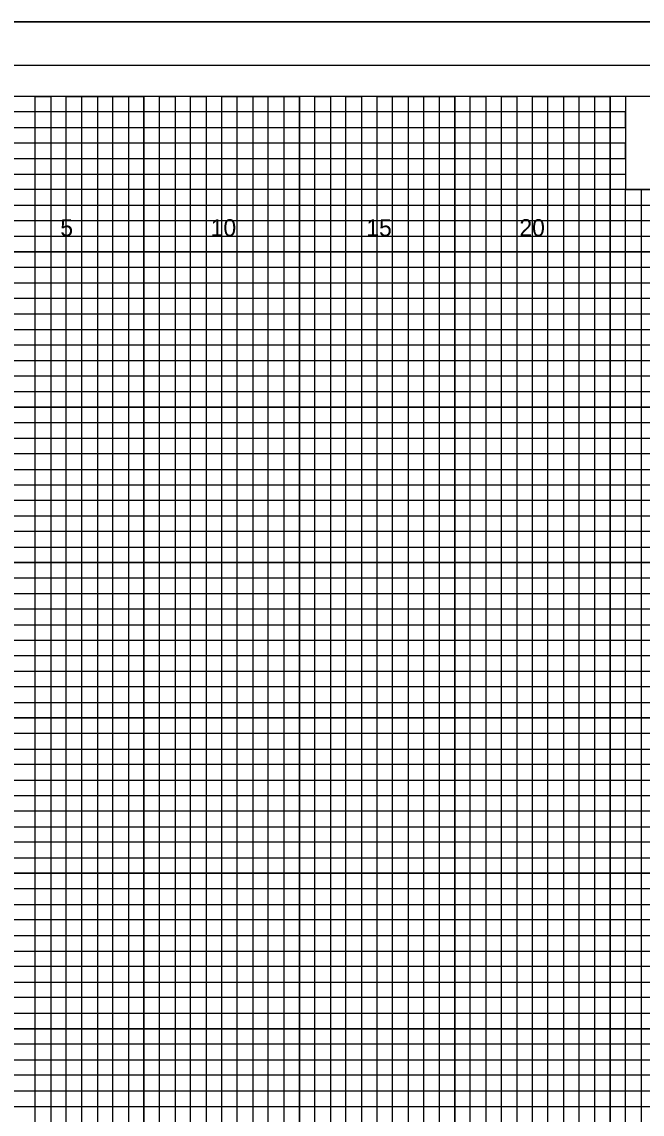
# Model space of a CAD drawing. Extents: x -4 to 103, y -2 to 209.
# Drawn here: x 54.82 to 74.78, y 103.08 to 138.22 of the extents above; entities that cross this region are included whole.
import ezdxf

# ---------------------------------------------------------------- set-up
doc = ezdxf.new("R2010")
doc.units = 0
for name, color, linetype in [('Old_Level_10', 7, 'Continuous'), ('Old_Level_16', 7, 'Continuous'), ('Old_Level_17', 7, 'Continuous'), ('Old_Level_3', 7, 'Continuous'), ('Old_Level_5', 7, 'Continuous'), ('Old_Level_6', 7, 'Continuous'), ('Old_Level_8', 7, 'Continuous'), ('Typical Curb CELL', 7, 'Continuous')]:
    doc.layers.add(name, color=color, linetype=linetype)

msp = doc.modelspace()

# ---------------------------------------------------------------- linework, layer by layer
at = {"layer": 'Old_Level_10'}
for p, q in [((56.25, 70.825), (56.25, 135.825)), ((58.75, 70.825), (58.75, 135.825)), ((61.25, 70.825), (61.25, 135.825)), ((63.75, 70.825), (63.75, 135.825)), ((66.25, 70.825), (66.25, 135.825)), ((68.75, 70.825), (68.75, 135.825)), ((71.25, 70.825), (71.25, 135.825)), ((73.75, 70.825), (73.75, 135.825)), ((0, 133.325), (74.25, 133.325)), ((0, 130.825), (102.5, 130.825)), ((0, 128.325), (102.5, 128.325)), ((0, 125.825), (102.5, 125.825)), ((0, 123.325), (102.5, 123.325)), ((0, 120.825), (102.5, 120.825)), ((0, 118.325), (102.5, 118.325)), ((0, 115.825), (102.5, 115.825)), ((0, 113.325), (102.5, 113.325)), ((0, 110.825), (102.5, 110.825)), ((0, 108.325), (102.5, 108.325)), ((0, 105.825), (102.5, 105.825)), ((0, 103.325), (102.5, 103.325))]:
    msp.add_line(p, q, dxfattribs=at)
at = {"layer": 'Old_Level_17'}
for points in [[(55.25, 70.825), (55.25, 135.825), (55.75, 135.825), (55.75, 70.825)], [(56.75, 70.825), (56.75, 135.825), (57.25, 135.825), (57.25, 70.825)], [(57.75, 70.825), (57.75, 135.825), (58.25, 135.825), (58.25, 70.825)], [(59.25, 70.825), (59.25, 135.825), (59.75, 135.825), (59.75, 70.825)], [(60.25, 70.825), (60.25, 135.825), (60.75, 135.825), (60.75, 70.825)], [(61.75, 70.825), (61.75, 135.825), (62.25, 135.825), (62.25, 70.825)], [(62.75, 70.825), (62.75, 135.825), (63.25, 135.825), (63.25, 70.825)], [(64.25, 70.825), (64.25, 135.825), (64.75, 135.825), (64.75, 70.825)], [(65.25, 70.825), (65.25, 135.825), (65.75, 135.825), (65.75, 70.825)], [(66.75, 70.825), (66.75, 135.825), (67.25, 135.825), (67.25, 70.825)], [(67.75, 70.825), (67.75, 135.825), (68.25, 135.825), (68.25, 70.825)], [(69.25, 70.825), (69.25, 135.825)], [(69.25, 135.825), (69.75, 135.825), (69.75, 70.825)], [(70.25, 70.825), (70.25, 135.825), (70.75, 135.825), (70.75, 70.825)], [(71.75, 70.825), (71.75, 135.825), (72.25, 135.825), (72.25, 70.825)], [(72.75, 70.825), (72.75, 135.825), (73.25, 135.825), (73.25, 70.825)], [(0, 132.825), (0, 133.825), (74.25, 133.825), (74.25, 134.325), (0, 134.325), (0, 134.825), (74.25, 134.825), (74.25, 135.325), (0, 135.325)], [(0, 132.325), (102.5, 132.325), (102.5, 132.825), (0, 132.825)], [(74.25, 70.825), (74.25, 132.825), (74.75, 132.825), (74.75, 70.825)], [(0, 131.325), (102.5, 131.325), (102.5, 131.825), (0, 131.825)], [(0, 129.825), (102.5, 129.825), (102.5, 130.325), (0, 130.325)], [(0, 128.825), (102.5, 128.825), (102.5, 129.325), (0, 129.325)], [(0, 127.325), (102.5, 127.325), (102.5, 127.825), (0, 127.825)], [(0, 126.325), (102.5, 126.325), (102.5, 126.825), (0, 126.825)], [(0, 124.825), (102.5, 124.825), (102.5, 125.325), (0, 125.325)], [(0, 123.825), (102.5, 123.825), (102.5, 124.325), (0, 124.325)], [(0, 122.325), (102.5, 122.325), (102.5, 122.825), (0, 122.825)], [(0, 121.325), (102.5, 121.325), (102.5, 121.825), (0, 121.825)], [(0, 119.825), (102.5, 119.825), (102.5, 120.325), (0, 120.325)], [(0, 118.825), (102.5, 118.825), (102.5, 119.325), (0, 119.325)], [(0, 117.325), (102.5, 117.325), (102.5, 117.825), (0, 117.825)], [(0, 116.325), (102.5, 116.325), (102.5, 116.825), (0, 116.825)], [(0, 114.825), (102.5, 114.825), (102.5, 115.325), (0, 115.325)], [(0, 113.825), (102.5, 113.825), (102.5, 114.325), (0, 114.325)], [(0, 112.325), (102.5, 112.325), (102.5, 112.825), (0, 112.825)], [(0, 111.325), (102.5, 111.325), (102.5, 111.825), (0, 111.825)], [(0, 109.825), (102.5, 109.825), (102.5, 110.325), (0, 110.325)], [(0, 108.825), (102.5, 108.825), (102.5, 109.325), (0, 109.325)], [(0, 107.325), (102.5, 107.325), (102.5, 107.825), (0, 107.825)], [(0, 106.325), (102.5, 106.325), (102.5, 106.825), (0, 106.825)], [(0, 104.825), (102.5, 104.825), (102.5, 105.325), (0, 105.325)], [(0, 103.825), (102.5, 103.825), (102.5, 104.325), (0, 104.325)]]:
    msp.add_lwpolyline(points, dxfattribs=at)
at = {"layer": 'Old_Level_3'}
msp.add_line((-3.5, 138.225), (103.4, 138.225), dxfattribs=at)
at = {"layer": 'Old_Level_5'}
msp.add_lwpolyline([(103.4, 138.225), (-3.5, 138.225), (-3.5, 68.4), (103.4, 68.4)], close=True, dxfattribs=at)
at = {"layer": 'Old_Level_6'}
for points in [[(102.5, 135.825), (0, 135.825), (0, 70.825), (102.5, 70.825)], [(83.75, 135.825), (74.25, 135.825), (74.25, 132.825), (83.75, 132.825)]]:
    msp.add_lwpolyline(points, close=True, dxfattribs=at)
at = {"layer": 'Old_Level_8'}
for points in [[(56.25, 70.825), (56.25, 135.825), (58.75, 135.825), (58.75, 70.825)], [(61.25, 70.825), (61.25, 135.825), (63.75, 135.825), (63.75, 70.825)], [(66.25, 70.825), (66.25, 135.825), (68.75, 135.825), (68.75, 70.825)], [(71.25, 70.825), (71.25, 135.825), (73.75, 135.825), (73.75, 70.825)], [(0, 133.325), (74.25, 133.325)], [(0, 128.325), (102.5, 128.325), (102.5, 130.825), (0, 130.825)], [(0, 123.325), (102.5, 123.325), (102.5, 125.825), (0, 125.825)], [(0, 118.325), (102.5, 118.325), (102.5, 120.825), (0, 120.825)], [(0, 113.325), (102.5, 113.325), (102.5, 115.825), (0, 115.825)], [(0, 108.325), (102.5, 108.325), (102.5, 110.825), (0, 110.825)], [(0, 103.325), (102.5, 103.325), (102.5, 105.825), (0, 105.825)]]:
    msp.add_lwpolyline(points, dxfattribs=at)
at = {"layer": 'Typical Curb CELL'}
msp.add_lwpolyline([(103, 136.825), (-2.8, 136.825), (-2.8, 69.825), (103, 69.825)], close=True, dxfattribs=at)

# ---------------------------------------------------------------- texts
at = {"layer": 'Old_Level_16'}
for s, p in [('5', (56.0574, 131.325)), ('10', (60.8971, 131.325)), ('15', (65.9057, 131.325)), ('20', (70.8312, 131.325))]:
    msp.add_text(s, height=0.55, dxfattribs=at).set_placement(p)

doc.saveas('drawing.dxf')
